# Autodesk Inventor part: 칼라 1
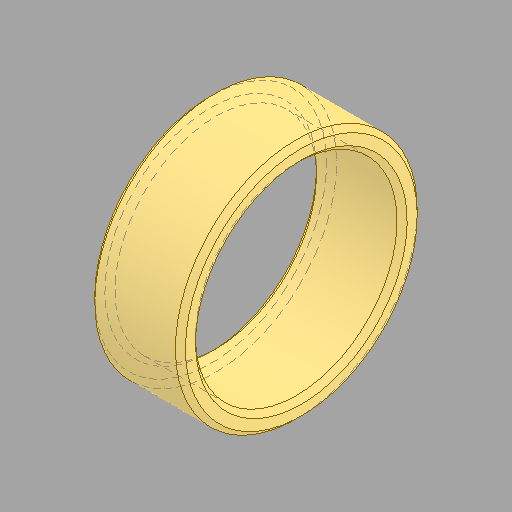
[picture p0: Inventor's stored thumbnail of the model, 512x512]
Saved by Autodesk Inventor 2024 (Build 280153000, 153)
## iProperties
Created: 2025-11
Part Number: 칼라 1
Material: 강철, 연강
Document SubType Name: Modeling
Designer: Edu09
Density: 7.85 g/cm^3
Appearance: 기본값
Author: jhkim
Sending System: Autodesk Inventor 2026
Preprocessor: ST-DEVELOPER v20.1
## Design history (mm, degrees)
feature "솔리드1"
node "솔리드2"
